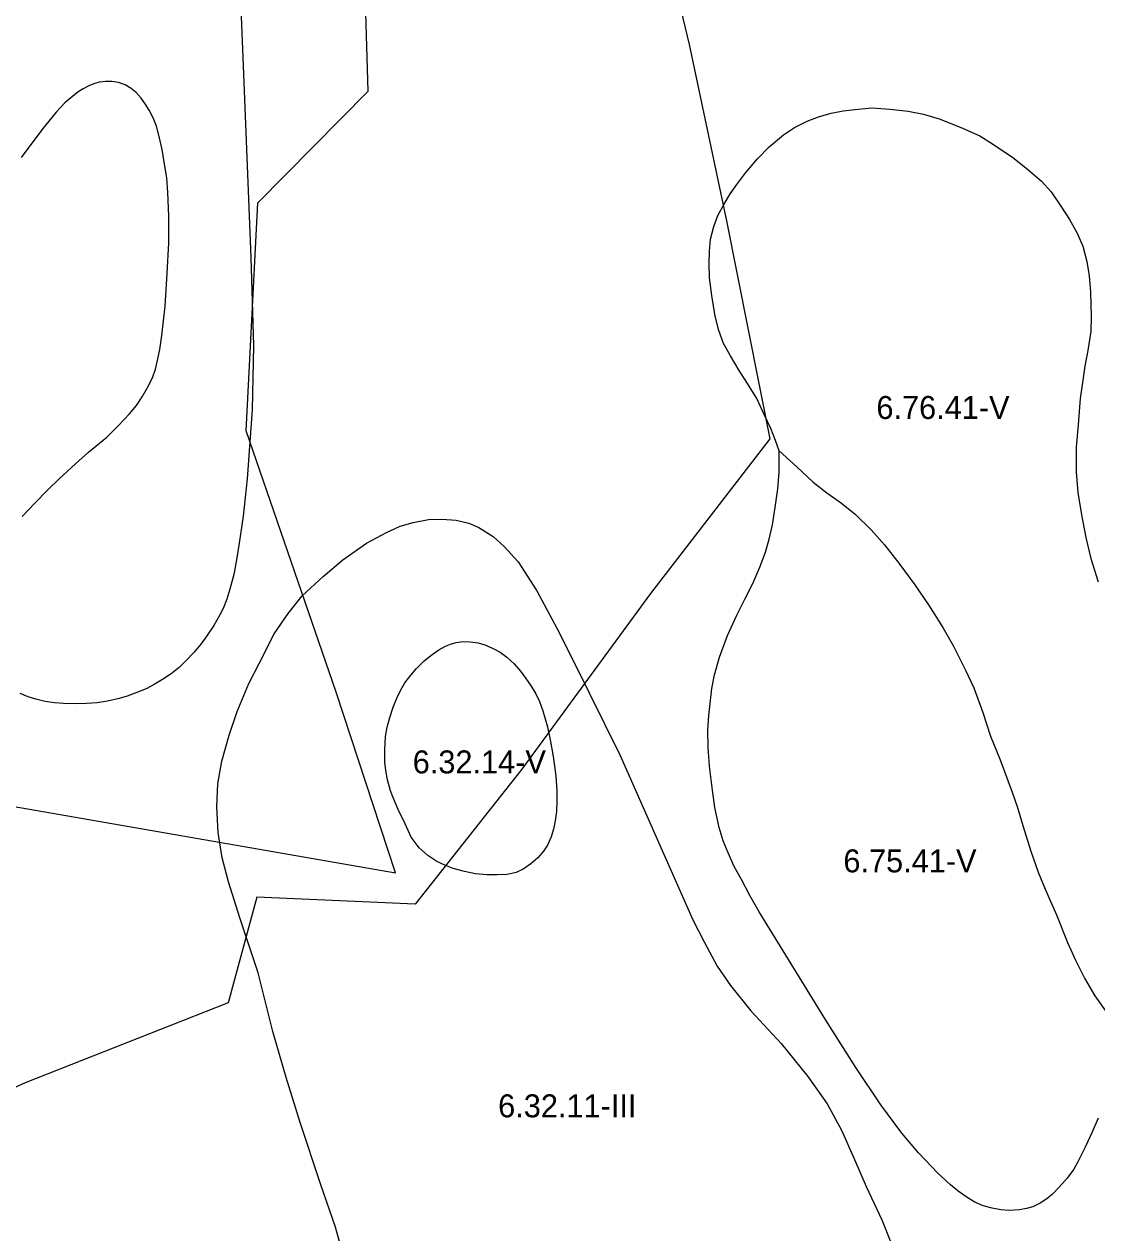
# Model space of a CAD drawing. Extents: x -555156 to -540209, y -1046851 to -1035695.
# Drawn here: x -544635 to -544168, y -1042117 to -1041591 of the extents above; entities that cross this region are included whole.
import ezdxf

# ---------------------------------------------------------------- set-up
doc = ezdxf.new("R2010")
doc.units = 0
for name, color, linetype in [('Vrstva 27', 7, 'Continuous'), ('Vrstva 28', 7, 'Continuous'), ('Vrstva 29', 7, 'Continuous')]:
    doc.layers.add(name, color=color, linetype=linetype)

msp = doc.modelspace()

# ---------------------------------------------------------------- linework, layer by layer
at = {"layer": 'Vrstva 28'}
for points in [[(-544542.44, -1041534.31), (-544539.68, -1041601.75), (-544536.08, -1041692.5), (-544534.86, -1041730.89), (-544535.4, -1041758.88), (-544536.61, -1041774.88), (-544537.58, -1041788.93), (-544539.28, -1041805.17), (-544541.02, -1041816.99), (-544542.19, -1041824.19), (-544543.44, -1041830.56), (-544545.17, -1041836.93), (-544546.41, -1041841.29), (-544548.08, -1041845.31), (-544549.46, -1041848.08), (-544552.09, -1041852.78), (-544555.2, -1041857.35), (-544557.76, -1041860.85), (-544560.67, -1041864.38), (-544564.4, -1041868.26), (-544567.17, -1041871.03), (-544570.7, -1041873.87), (-544574.51, -1041876.29), (-544578.04, -1041878.44), (-544581.64, -1041880.31), (-544585.65, -1041881.97), (-544589.8, -1041883.56), (-544593.4, -1041884.6), (-544598.38, -1041885.78), (-544602.88, -1041886.47), (-544607.59, -1041886.82), (-544611.81, -1041886.95), (-544617.55, -1041886.82), (-544621.43, -1041886.47), (-544625.51, -1041885.92), (-544629.66, -1041884.81), (-544632.93, -1041883.87), (-544636.39, -1041882.35)], [(-544581.13, -1041749.41), (-544578.85, -1041744.98), (-544577.46, -1041741.17), (-544576.77, -1041737.9), (-544575.68, -1041732.57), (-544574.71, -1041726.51), (-544573.37, -1041713.78), (-544572.41, -1041699.49), (-544571.74, -1041686.07), (-544571.74, -1041674.56), (-544572.22, -1041664.26), (-544572.59, -1041657.83), (-544573.78, -1041650.94), (-544574.68, -1041645.47), (-544575.93, -1041639.8), (-544577.1, -1041635.36), (-544578.49, -1041631.69), (-544580.29, -1041628.37), (-544582.09, -1041625.53), (-544583.75, -1041623.18), (-544585.89, -1041620.69), (-544588.18, -1041618.95), (-544590.8, -1041617.29), (-544593.57, -1041616.32), (-544596.48, -1041615.91), (-544599.32, -1041615.84), (-544601.88, -1041616.18), (-544604.02, -1041616.74), (-544606.51, -1041617.71), (-544609.07, -1041619.09), (-544611.22, -1041620.41), (-544614.4, -1041622.97), (-544616.96, -1041625.12), (-544620.77, -1041629.2), (-544626.51, -1041636.32), (-544636.08, -1041648.92)], [(-544305.99, -1041776.73), (-544307.59, -1041772.24), (-544309.53, -1041767.05), (-544312.3, -1041761.23), (-544314.1, -1041757.35), (-544315.72, -1041753.95), (-544319.72, -1041747.41), (-544323.35, -1041741.71), (-544327.23, -1041735.41), (-544330.25, -1041729.96), (-544332.31, -1041724.26), (-544333.83, -1041718.14), (-544335.28, -1041709.05), (-544336.25, -1041701.42), (-544336.49, -1041695.12), (-544336.37, -1041689.79), (-544335.89, -1041684.58), (-544334.43, -1041679), (-544332.62, -1041674.16), (-544329.95, -1041669.31), (-544327.29, -1041664.83), (-544324.38, -1041660.71), (-544320.51, -1041655.5), (-544315.42, -1041649.56), (-544310.33, -1041644.35), (-544304.03, -1041639.14), (-544299.33, -1041635.89), (-544293.76, -1041633.22), (-544288.79, -1041631.28), (-544283.34, -1041629.71), (-544278.13, -1041628.62), (-544271.59, -1041627.89), (-544265.42, -1041627.41), (-544257.79, -1041627.89)], [(-544257.79, -1041627.89), (-544249.79, -1041628.74), (-544243.13, -1041630.07), (-544235.87, -1041632.25), (-544226.18, -1041636.13), (-544218.67, -1041639.52), (-544212.61, -1041643.28), (-544204.26, -1041648.98), (-544197.84, -1041654.06), (-544191.73, -1041659.28), (-544187.49, -1041663.89), (-544183.01, -1041670.55), (-544179.62, -1041676), (-544176.23, -1041681.94), (-544173.69, -1041687.52), (-544171.99, -1041694.3), (-544171.02, -1041700.48), (-544170.42, -1041707.63), (-544170.17, -1041718.17), (-544170.29, -1041724.72), (-544171.63, -1041733.08), (-544172.84, -1041739.86), (-544173.93, -1041746.89), (-544174.93, -1041753.97), (-544175.77, -1041765.36), (-544176.62, -1041775.06), (-544176.62, -1041785.84), (-544175.9, -1041794.81), (-544174.32, -1041804.62), (-544172.5, -1041814.44), (-544170.2, -1041823.65), (-544167.06, -1041833.7)], [(-544635.55, -1041805.26), (-544630.23, -1041799.69), (-544624.41, -1041793.75), (-544619.42, -1041788.88), (-544612.39, -1041782.34), (-544606.7, -1041777.25), (-544598.71, -1041770.81), (-544593.79, -1041765.82), (-544588.81, -1041760.56), (-544585.84, -1041756.96), (-544583.34, -1041753.15), (-544581.13, -1041749.41)], [(-544167.05, -1042067.36), (-544169.84, -1042073.67), (-544172.74, -1042079.97), (-544175.89, -1042086.39), (-544177.73, -1042089.5), (-544180.57, -1042093.45), (-544184.03, -1042097.4), (-544187.01, -1042100.44), (-544189.36, -1042102.52), (-544192.27, -1042104.39), (-544195.59, -1042105.98), (-544198.22, -1042106.68), (-544201.4, -1042107.23), (-544205.76, -1042107.51), (-544209.5, -1042107.3), (-544213.23, -1042106.61), (-544217.11, -1042105.5), (-544220.78, -1042103.98), (-544224.17, -1042101.9), (-544228.04, -1042099.2), (-544231.37, -1042096.36), (-544236.9, -1042091.24), (-544245.28, -1042082.44), (-544252.52, -1042073.84), (-544261.72, -1042061.48), (-544272.62, -1042045.24), (-544285.7, -1042024.64), (-544314.72, -1041977.53), (-544318.72, -1041970.32), (-544322.35, -1041963.41), (-544325.5, -1041957.72), (-544328.16, -1041951.78), (-544330.34, -1041946.57), (-544332.04, -1041940.75), (-544333.98, -1041932.03), (-544335.07, -1041924.52), (-544336.28, -1041914.1), (-544336.88, -1041905.98), (-544337.09, -1041898.36), (-544336.61, -1041891.94), (-544335.28, -1041880.18), (-544334.19, -1041874.25), (-544332.01, -1041866.61), (-544328.5, -1041857.16), (-544324.38, -1041848.31), (-544320.87, -1041841.29), (-544317.48, -1041834.5), (-544314.45, -1041827.35), (-544311.9, -1041820.81), (-544310.35, -1041815.26), (-544308.9, -1041808.96), (-544307.69, -1041801.45), (-544306.48, -1041793.33), (-544305.99, -1041786.06), (-544305.99, -1041776.73)], [(-544305.99, -1041776.73), (-544298.12, -1041783.88)], [(-544298.12, -1041783.88), (-544291.1, -1041790.42), (-544285.16, -1041795.03), (-544278.86, -1041799.51), (-544272.81, -1041804.24), (-544265.91, -1041811.14), (-544260.09, -1041817.69), (-544253.92, -1041825.69), (-544246.89, -1041835.02), (-544241.02, -1041843.72), (-544234.72, -1041853.65), (-544230, -1041861.77), (-544224.79, -1041872.19), (-544221.28, -1041879.95), (-544217.28, -1041890.61), (-544213.89, -1041901.03), (-544209.77, -1041911.33), (-544204.51, -1041925.43), (-544202.24, -1041932.07), (-544199.94, -1041939.82), (-544196.43, -1041951.09), (-544193.16, -1041960.18), (-544190.13, -1041967.57), (-544185.23, -1041978.84), (-544180.38, -1041990.84), (-544176.99, -1041998.47), (-544172.99, -1042006.35), (-544168.51, -1042014.1), (-544162.46, -1042022.58)], [(-544495.72, -1042127.48), (-544499.18, -1042114.88), (-544505.62, -1042095.9), (-544514.52, -1042069.18), (-544520.66, -1042049.67), (-544526.39, -1042029.53), (-544532.8, -1042004.07), (-544540.64, -1041980.53), (-544545.73, -1041964.41), (-544548.48, -1041954.02), (-544550.18, -1041943), (-544550.81, -1041931.76), (-544550.39, -1041921.79), (-544548.69, -1041911.83), (-544545.51, -1041900.59), (-544541.91, -1041890.2), (-544536.82, -1041878.11), (-544532.45, -1041869.36), (-544525.88, -1041856.43), (-544519.74, -1041847.52), (-544513.59, -1041839.89), (-544504.48, -1041831.41), (-544496, -1041824.2), (-544485.62, -1041816.99), (-544476.93, -1041812.32), (-544470.99, -1041809.56), (-544465.27, -1041807.93), (-544458.61, -1041806.6), (-544452.92, -1041806.47), (-544446.62, -1041806.96)], [(-544446.62, -1041806.96), (-544441.05, -1041808.29), (-544436.69, -1041810.11), (-544430.51, -1041813.99), (-544425.67, -1041818.35), (-544419.61, -1041825.01), (-544411.5, -1041837.62), (-544402.78, -1041853.97), (-544395.51, -1041868.39), (-544375.17, -1041909.46), (-544343.59, -1041980.92), (-544338.64, -1041990.5), (-544332.92, -1042001.1), (-544327.2, -1042009.58), (-544318.29, -1042020.61), (-544305.15, -1042034.82), (-544293.5, -1042049.24), (-544285.02, -1042061.11), (-544278.87, -1042072.56), (-544273.15, -1042085.29), (-544268.07, -1042097.16), (-544261.28, -1042111.58), (-544255.35, -1042126.64)], [(-544440.48, -1041859.84), (-544437.04, -1041860.32), (-544434.08, -1041861.27), (-544430.48, -1041862.73), (-544427.39, -1041864.39), (-544424.59, -1041866.53), (-544421.38, -1041869.46), (-544418.58, -1041872.74), (-544416.24, -1041875.83), (-544413.99, -1041879.15), (-544411.97, -1041882.51), (-544410.35, -1041885.88), (-544408.88, -1041889.96), (-544406.88, -1041896.96), (-544405.49, -1041903.26), (-544404.32, -1041909.9), (-544403.28, -1041918.28), (-544402.79, -1041924.79), (-544402.79, -1041929.36), (-544402.97, -1041933.79), (-544403.52, -1041937.81), (-544404.28, -1041941.48), (-544405.25, -1041944.8), (-544406.91, -1041948.4), (-544408.57, -1041951.03), (-544411.06, -1041954.01), (-544414.11, -1041956.64), (-544417.5, -1041958.86), (-544420.55, -1041960.31), (-544424.42, -1041961.28), (-544428.71, -1041961.42), (-544433.21, -1041961.42), (-544438.19, -1041961), (-544443.04, -1041959.97), (-544447.95, -1041958.58), (-544451.55, -1041957.13), (-544455.01, -1041955.6), (-544458.95, -1041952.9), (-544462.69, -1041949.65), (-544466.15, -1041944.94), (-544468.88, -1041939.18), (-544471.93, -1041932.87), (-544474.14, -1041927.4), (-544475.26, -1041924.84), (-544476.57, -1041920), (-544477.27, -1041915.98), (-544477.61, -1041912.24), (-544477.68, -1041906.91), (-544477.34, -1041901.09), (-544476.64, -1041897.01), (-544475.47, -1041892.78), (-544474.01, -1041888.28), (-544472.42, -1041884.41), (-544470.76, -1041880.87), (-544468.96, -1041877.69), (-544466.4, -1041874.37), (-544463.91, -1041871.46), (-544460.59, -1041868.2), (-544457.06, -1041865.36), (-544454.17, -1041863.4), (-544451.28, -1041861.74), (-544449.1, -1041860.87), (-544446.61, -1041860.2)], [(-544446.61, -1041860.2), (-544443.77, -1041859.8), (-544440.48, -1041859.84)]]:
    msp.add_lwpolyline(points, dxfattribs=at)
at = {"layer": 'Vrstva 29'}
for points in [[(-544357.718018, -1041547.11499), (-544345.106995, -1041599.81897), (-544328.90802, -1041676.575989), (-544310.086975, -1041771.429016), (-544361.945007, -1041838.867004), (-544417.97998, -1041915.335999), (-544464.419006, -1041974.11499), (-544533.328979, -1041971.086975), (-544545.867004, -1042017.049988), (-544634.208984, -1042051.930969), (-544723.911011, -1042093.055908)], [(-544649.171997, -1041929.914001), (-544473.088013, -1041960.538025), (-544498.805908, -1041881.849976), (-544538.03302, -1041767.963013), (-544532.950012, -1041668.768982), (-544484.916992, -1041620.085999), (-544487.161011, -1041546.960022)]]:
    msp.add_lwpolyline(points, dxfattribs=at)

# ---------------------------------------------------------------- texts
at = {"layer": 'Vrstva 27'}
for s, p in [('6.76.41-V', (-544263.641006, -1041762.84)), ('6.32.14-V', (-544465.520884, -1041917.2)), ('6.75.41-V', (-544278.011006, -1041960.3)), ('6.32.11-III', (-544428.326548, -1042066.98))]:
    msp.add_text(s, height=10, dxfattribs=at).set_placement(p)

doc.saveas('drawing.dxf')
